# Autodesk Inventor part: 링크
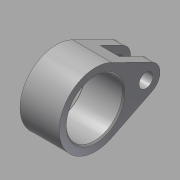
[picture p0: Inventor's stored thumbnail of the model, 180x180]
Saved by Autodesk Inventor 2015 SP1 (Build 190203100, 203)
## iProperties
Created: 2016-02
Part Number: 링크
Material: 강철, 연강
Document SubType Name: Modeling
Designer: test
Density: 1 g/cm^3
Appearance: 강철
Author: test
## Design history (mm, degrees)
sketch "스케치1"
  geometry: L1 (20.222, 4.479)-(5.778, 11.645); L2 (20.222, -4.479)-(5.778, -11.645); A1 r 13 centre (0, 0) between (5.778, 11.645) and (5.778, -11.645); A2 r 5 centre (18, 0) between (20.222, -4.479) and (20.222, 4.479); 1 further point
  constraints: 4 end point, 4 point on circle, 4 tangent, 2 centre point, 1 coincident, 1 horizontal alignment
  dimensions: "d0" = 18 distance of point (0, 0) A2.centre; "d1" = 13 radius of A1; "d2" = 5 radius of A2
extrude "돌출1" new body sketch "스케치1" stored distance "d3" = 14; taper "d4" = 0 deg
sketch "스케치2"
  geometry: C1 r 10 at (0, 0); 1 further point
  constraints: 1 centre point, 1 coincident
  dimensions: "d5" = 20 diameter of C1
extrude "돌출2" cut sketch "스케치2" stored distance "d6" = 14; taper "d7" = 0 deg
sketch "스케치3"
  geometry: C1 r 2.5 at (18, 0); A1 r 5 centre (18, 0) between (20.222, -4.479) and (20.222, 4.479) reference; 1 further point
  constraints: 1 centre point, 1 coincident
  dimensions: "d8" = 5 diameter of C1
extrude "돌출3" cut sketch "스케치3" stored distance "d9" = 14; taper "d10" = 0 deg
sketch "스케치4"
  geometry: L1 (20.222, -4.479)-(5.778, -11.645) reference; L2 (5.778, 11.645)-(20.222, 4.479) reference; L3 (12, 8.558)-(12, -8.558); C1 r 2.5 at (18, 0) reference; C2 r 10 at (0, 0) reference; A1 r 13 centre (0, 0) between (5.778, 11.645) and (5.778, -11.645) reference; A2 r 5 centre (18, 0) between (20.222, -4.479) and (20.222, 4.479) reference; 1 further point
  constraints: 2 end point, 2 point on line, 1 vertical
  dimensions: "d11" = 12 distance from line of L3 point (0, 0)
extrude "돌출4" cut sketch "스케치4" stored distance "d12" = 7; taper "d13" = 0 deg
chamfer "모따기1" distance "d14" = 0.5; stored, may be unused: second distance "d15" = 2, angle "d16" = 45 deg
node "솔리드1"
node "절단 모서리 투영1"
